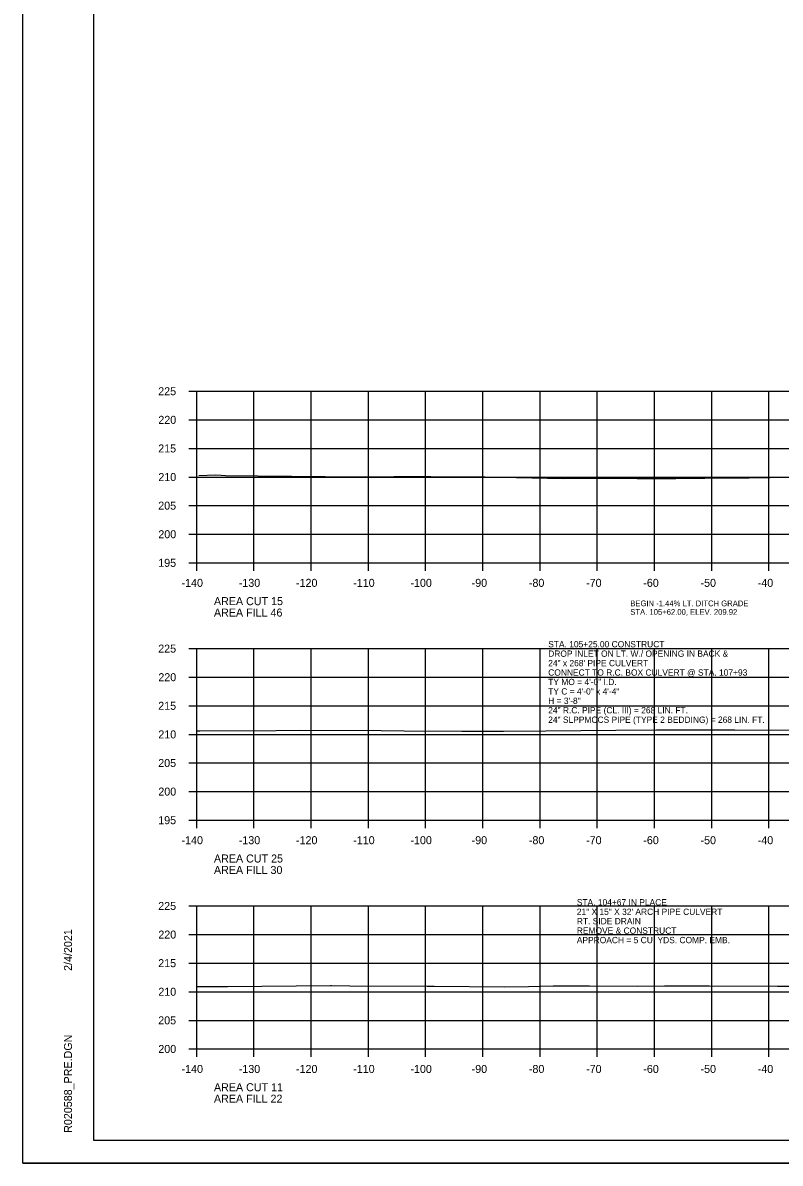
# Model space of a CAD drawing. Extents: x 1368968 to 1369915, y 377395 to 380381.
# Drawn here: x 1368967.7 to 1369100.1, y 378687.7 to 378887.1 of the extents above; entities that cross this region are included whole.
import ezdxf

# ---------------------------------------------------------------- set-up
doc = ezdxf.new("R2010")
doc.units = 0
for name, color, linetype in [('Default', 7, 'Continuous'), ('S_BREAKLINE_ANNOT', 7, 'Continuous'), ('S_BRIDGE', 7, 'Continuous'), ('S_BRIDGE_ANNOT', 7, 'Continuous'), ('S_CONTOUR_MAJOR', 7, 'Continuous'), ('S_CTL_TABLE', 7, 'Continuous'), ('S_DITCHLINE_ANNOT', 7, 'Continuous'), ('S_DROP_INLET', 7, 'Continuous')]:
    doc.layers.add(name, color=color, linetype=linetype)

msp = doc.modelspace()

# ---------------------------------------------------------------- linework, layer by layer
at = {"layer": 'S_BREAKLINE_ANNOT'}
for p, q in [((1368996.73, 378822.7), (1368998.13, 378822.7)), ((1368998.13, 378792.7), (1368998.13, 378822.7)), ((1368996.73, 378817.7), (1368998.13, 378817.7)), ((1368996.73, 378812.7), (1368998.13, 378812.7)), ((1368996.73, 378807.7), (1368998.13, 378807.7)), ((1368996.73, 378802.7), (1368998.13, 378802.7)), ((1368996.73, 378797.7), (1368998.13, 378797.7)), ((1368996.73, 378792.7), (1368998.13, 378792.7)), ((1368998.13, 378792.7), (1369278.13, 378792.7)), ((1368998.13, 378791.3), (1368998.13, 378792.7)), ((1369008.13, 378791.3), (1369008.13, 378792.7)), ((1369018.13, 378791.3), (1369018.13, 378792.7)), ((1369028.13, 378791.3), (1369028.13, 378792.7)), ((1369038.13, 378791.3), (1369038.13, 378792.7)), ((1369048.13, 378791.3), (1369048.13, 378792.7)), ((1369058.13, 378791.3), (1369058.13, 378792.7)), ((1369068.13, 378791.3), (1369068.13, 378792.7)), ((1369078.13, 378791.3), (1369078.13, 378792.7)), ((1369088.13, 378791.3), (1369088.13, 378792.7)), ((1369098.13, 378791.3), (1369098.13, 378792.7)), ((1368996.73, 378777.7), (1368998.13, 378777.7)), ((1368998.13, 378747.7), (1368998.13, 378777.7)), ((1368996.73, 378772.7), (1368998.13, 378772.7)), ((1368996.73, 378767.7), (1368998.13, 378767.7)), ((1368996.73, 378762.7), (1368998.13, 378762.7)), ((1368996.73, 378757.7), (1368998.13, 378757.7)), ((1368996.73, 378752.7), (1368998.13, 378752.7)), ((1368996.73, 378747.7), (1368998.13, 378747.7)), ((1368998.13, 378747.7), (1369278.13, 378747.7)), ((1368998.13, 378746.3), (1368998.13, 378747.7)), ((1369008.13, 378746.3), (1369008.13, 378747.7)), ((1369018.13, 378746.3), (1369018.13, 378747.7)), ((1369028.13, 378746.3), (1369028.13, 378747.7)), ((1369038.13, 378746.3), (1369038.13, 378747.7)), ((1369048.13, 378746.3), (1369048.13, 378747.7)), ((1369058.13, 378746.3), (1369058.13, 378747.7)), ((1369068.13, 378746.3), (1369068.13, 378747.7)), ((1369078.13, 378746.3), (1369078.13, 378747.7)), ((1369088.13, 378746.3), (1369088.13, 378747.7)), ((1369098.13, 378746.3), (1369098.13, 378747.7)), ((1368996.73, 378732.7), (1368998.13, 378732.7)), ((1368998.13, 378707.7), (1368998.13, 378732.7)), ((1368996.73, 378727.7), (1368998.13, 378727.7)), ((1368996.73, 378722.7), (1368998.13, 378722.7)), ((1368996.73, 378717.7), (1368998.13, 378717.7)), ((1368996.73, 378712.7), (1368998.13, 378712.7)), ((1368996.73, 378707.7), (1368998.13, 378707.7)), ((1368998.13, 378707.7), (1369278.13, 378707.7)), ((1368998.13, 378706.3), (1368998.13, 378707.7)), ((1369008.13, 378706.3), (1369008.13, 378707.7)), ((1369018.13, 378706.3), (1369018.13, 378707.7)), ((1369028.13, 378706.3), (1369028.13, 378707.7)), ((1369038.13, 378706.3), (1369038.13, 378707.7)), ((1369048.13, 378706.3), (1369048.13, 378707.7)), ((1369058.13, 378706.3), (1369058.13, 378707.7)), ((1369068.13, 378706.3), (1369068.13, 378707.7)), ((1369078.13, 378706.3), (1369078.13, 378707.7)), ((1369088.13, 378706.3), (1369088.13, 378707.7)), ((1369098.13, 378706.3), (1369098.13, 378707.7))]:
    msp.add_line(p, q, dxfattribs=at)
at = {"layer": 'S_BRIDGE_ANNOT'}
for p, q in [((1368980.13, 378691.7), (1368980.13, 378897.16)), ((1368980.13, 378691.7), (1368980.13, 378691.7)), ((1369296.31, 378691.7), (1368980.13, 378691.7))]:
    msp.add_line(p, q, dxfattribs=at)
at = {"layer": 'S_CTL_TABLE'}
for points in [[(1368998.49, 378807.95), (1369001.46, 378808.06), (1369002.38, 378808.04), (1369003.16, 378807.95), (1369008.8, 378807.9), (1369026.43, 378807.75), (1369028.74, 378807.73), (1369032.56, 378807.78), (1369039.05, 378807.78), (1369048.56, 378807.72), (1369062.14, 378807.47), (1369062.82, 378807.48), (1369075.07, 378807.45), (1369081.09, 378807.46), (1369081.86, 378807.46), (1369092.02, 378807.54), (1369094.58, 378807.57), (1369094.68, 378807.57), (1369102.03, 378807.68)], [(1368998.13, 378763.31), (1368998.68, 378763.31), (1369012.03, 378763.38), (1369016.19, 378763.42), (1369030.35, 378763.38), (1369034.39, 378763.35), (1369044.47, 378763.29), (1369051.73, 378763.24), (1369059.11, 378763.33), (1369071.37, 378763.42), (1369078.46, 378763.49), (1369081.62, 378763.51), (1369092.18, 378763.48), (1369103.18, 378763.42)], [(1368998.13, 378718.62), (1369003, 378718.62), (1369003.48, 378718.62), (1369021.5, 378718.78), (1369021.69, 378718.78), (1369024.86, 378718.76), (1369038.41, 378718.67), (1369039, 378718.67), (1369039.64, 378718.66), (1369051.92, 378718.57), (1369056.1, 378718.63), (1369060.43, 378718.73), (1369066.79, 378718.74), (1369075.19, 378718.7), (1369079.89, 378718.73), (1369087.66, 378718.71), (1369099.64, 378718.66), (1369104.13, 378718.65)]]:
    msp.add_lwpolyline(points, dxfattribs=at)
at = {"layer": 'S_DITCHLINE_ANNOT'}
for p, q in [((1368998.13, 378822.7), (1369278.13, 378822.7)), ((1368998.13, 378792.7), (1368998.13, 378822.7)), ((1369008.13, 378792.7), (1369008.13, 378822.7)), ((1369018.13, 378792.7), (1369018.13, 378822.7)), ((1369028.13, 378792.7), (1369028.13, 378822.7)), ((1369038.13, 378792.7), (1369038.13, 378822.7)), ((1369048.13, 378792.7), (1369048.13, 378822.7)), ((1369058.13, 378792.7), (1369058.13, 378822.7)), ((1369068.13, 378792.7), (1369068.13, 378822.7)), ((1369078.13, 378792.7), (1369078.13, 378822.7)), ((1369088.13, 378792.7), (1369088.13, 378822.7)), ((1369098.13, 378792.7), (1369098.13, 378822.7)), ((1368998.13, 378817.7), (1369278.13, 378817.7)), ((1368998.13, 378812.7), (1369278.13, 378812.7)), ((1368998.13, 378807.7), (1369278.13, 378807.7)), ((1368998.13, 378802.7), (1369278.13, 378802.7)), ((1368998.13, 378797.7), (1369278.13, 378797.7)), ((1368998.13, 378792.7), (1369278.13, 378792.7)), ((1368998.13, 378777.7), (1369278.13, 378777.7)), ((1368998.13, 378747.7), (1368998.13, 378777.7)), ((1369008.13, 378747.7), (1369008.13, 378777.7)), ((1369018.13, 378747.7), (1369018.13, 378777.7)), ((1369028.13, 378747.7), (1369028.13, 378777.7)), ((1369038.13, 378747.7), (1369038.13, 378777.7)), ((1369048.13, 378747.7), (1369048.13, 378777.7)), ((1369058.13, 378747.7), (1369058.13, 378777.7)), ((1369068.13, 378747.7), (1369068.13, 378777.7)), ((1369078.13, 378747.7), (1369078.13, 378777.7)), ((1369088.13, 378747.7), (1369088.13, 378777.7)), ((1369098.13, 378747.7), (1369098.13, 378777.7)), ((1368998.13, 378772.7), (1369278.13, 378772.7)), ((1368998.13, 378767.7), (1369278.13, 378767.7)), ((1368998.13, 378762.7), (1369278.13, 378762.7)), ((1368998.13, 378757.7), (1369278.13, 378757.7)), ((1368998.13, 378752.7), (1369278.13, 378752.7)), ((1368998.13, 378747.7), (1369278.13, 378747.7)), ((1368998.13, 378732.7), (1369278.13, 378732.7)), ((1368998.13, 378707.7), (1368998.13, 378732.7)), ((1369008.13, 378707.7), (1369008.13, 378732.7)), ((1369018.13, 378707.7), (1369018.13, 378732.7)), ((1369028.13, 378707.7), (1369028.13, 378732.7)), ((1369038.13, 378707.7), (1369038.13, 378732.7)), ((1369048.13, 378707.7), (1369048.13, 378732.7)), ((1369058.13, 378707.7), (1369058.13, 378732.7)), ((1369068.13, 378707.7), (1369068.13, 378732.7)), ((1369078.13, 378707.7), (1369078.13, 378732.7)), ((1369088.13, 378707.7), (1369088.13, 378732.7)), ((1369098.13, 378707.7), (1369098.13, 378732.7)), ((1368998.13, 378727.7), (1369278.13, 378727.7)), ((1368998.13, 378722.7), (1369278.13, 378722.7)), ((1368998.13, 378717.7), (1369278.13, 378717.7)), ((1368998.13, 378712.7), (1369278.13, 378712.7)), ((1368998.13, 378707.7), (1369278.13, 378707.7))]:
    msp.add_line(p, q, dxfattribs=at)
at = {"layer": 'S_DROP_INLET'}
msp.add_line((1368967.73, 378687.73), (1369301.07, 378687.73), dxfattribs=at)
for points in [[(1368967.73, 378901.06), (1369301.07, 378901.06), (1369301.07, 378687.72), (1368967.73, 378687.72)], [(1369214.05, 378897.16), (1369214.05, 378887.28), (1369249.79, 378887.28), (1369249.79, 378884.36), (1369272.99, 378884.36), (1369272.99, 378860.03), (1369296.31, 378860.03), (1369296.31, 378691.7), (1368980.13, 378691.7), (1368980.13, 378897.16)]]:
    msp.add_lwpolyline(points, close=True, dxfattribs=at)

# ---------------------------------------------------------------- texts
at = {"layer": 'Default'}
for s, p in [('STA. 105+25.00 CONSTRUCT', (1369059.55, 378777.92)), ('DROP INLET ON LT. W./ OPENING IN BACK &', (1369059.55, 378776.27)), ('24" x 268\' PIPE CULVERT', (1369059.55, 378774.62)), ('CONNECT TO R.C. BOX CULVERT @ STA. 107+93 ', (1369059.55, 378772.97)), ('TY MO = 4\'-0" I.D.', (1369059.55, 378771.32)), ('TY C = 4\'-0" x 4\'-4"', (1369059.55, 378769.67)), ('H = 3\'-8"', (1369059.55, 378768.02)), ('24" R.C. PIPE (CL. III) = 268 LIN. FT.', (1369059.55, 378766.37)), ('24" SLPPMCCS PIPE (TYPE 2 BEDDING) = 268 LIN. FT.', (1369059.55, 378764.72)), ('STA. 104+67 IN PLACE', (1369064.55, 378732.79)), ('21" X 15" X 32\' ARCH PIPE CULVERT', (1369064.55, 378731.14)), ('RT. SIDE DRAIN', (1369064.55, 378729.49)), ('REMOVE & CONSTRUCT ', (1369064.55, 378727.84)), ('APPROACH = 5 CU. YDS. COMP. EMB.', (1369064.55, 378726.19))]:
    msp.add_text(s, height=1.1, dxfattribs=at).set_placement(p)
at = {"layer": 'S_BRIDGE'}
for s, p in [('225', (1368991.39, 378822)), ('220', (1368991.41, 378817)), ('215', (1368991.39, 378812)), ('210', (1368991.41, 378807)), ('205', (1368991.39, 378802)), ('200', (1368991.41, 378797)), ('195', (1368991.39, 378792)), ('-140', (1368995.47, 378788.5)), ('-130', (1369005.47, 378788.5)), ('-120', (1369015.47, 378788.5)), ('-110', (1369025.47, 378788.5)), ('-100', (1369035.47, 378788.5)), ('-90', (1369046.17, 378788.5)), ('-80', (1369056.17, 378788.5)), ('-70', (1369066.17, 378788.5)), ('-60', (1369076.17, 378788.5)), ('-50', (1369086.17, 378788.5)), ('-40', (1369096.17, 378788.5)), ('AREA CUT 15', (1369001.13, 378785.3)), ('AREA FILL 46', (1369001.13, 378783.3)), ('225', (1368991.39, 378777)), ('220', (1368991.41, 378772)), ('215', (1368991.39, 378767)), ('210', (1368991.41, 378762)), ('205', (1368991.39, 378757)), ('200', (1368991.41, 378752)), ('195', (1368991.39, 378747)), ('-140', (1368995.47, 378743.5)), ('-130', (1369005.47, 378743.5)), ('-120', (1369015.47, 378743.5)), ('-110', (1369025.47, 378743.5)), ('-100', (1369035.47, 378743.5)), ('-90', (1369046.17, 378743.5)), ('-80', (1369056.17, 378743.5)), ('-70', (1369066.17, 378743.5)), ('-60', (1369076.17, 378743.5)), ('-50', (1369086.17, 378743.5)), ('-40', (1369096.17, 378743.5)), ('AREA CUT 25', (1369001.13, 378740.3)), ('AREA FILL 30', (1369001.13, 378738.3)), ('225', (1368991.39, 378732)), ('220', (1368991.41, 378727)), ('215', (1368991.39, 378722)), ('210', (1368991.41, 378717)), ('205', (1368991.39, 378712)), ('200', (1368991.41, 378707)), ('-140', (1368995.47, 378703.5)), ('-130', (1369005.47, 378703.5)), ('-120', (1369015.47, 378703.5)), ('-110', (1369025.47, 378703.5)), ('-100', (1369035.47, 378703.5)), ('-90', (1369046.17, 378703.5)), ('-80', (1369056.17, 378703.5)), ('-70', (1369066.17, 378703.5)), ('-60', (1369076.17, 378703.5)), ('-50', (1369086.17, 378703.5)), ('-40', (1369096.17, 378703.5)), ('AREA CUT 11', (1369001.13, 378700.3)), ('AREA FILL 22', (1369001.13, 378698.3))]:
    msp.add_text(s, height=1.4, dxfattribs=at).set_placement(p)
at = {"layer": 'S_BRIDGE_ANNOT'}
for s, p in [('2/4/2021', (1368976.32, 378721.35)), ('R020588_PRE.DGN', (1368976.32, 378693.03))]:
    msp.add_text(s, height=1.4, rotation=90, dxfattribs=at).set_placement(p)
at = {"layer": 'S_CONTOUR_MAJOR'}
for s, p in [('BEGIN -1.44% LT. DITCH GRADE', (1369073.89, 378785.11)), ('BEGIN -1.44% LT. DITCH GRADE', (1369073.89, 378785.11)), ('BEGIN -1.44% LT. DITCH GRADE', (1369073.89, 378785.11)), ('STA. 105+62.00, ELEV. 209.92', (1369073.9, 378783.61)), ('STA. 105+62.00, ELEV. 209.92', (1369073.9, 378783.61)), ('STA. 105+62.00, ELEV. 209.92', (1369073.9, 378783.61))]:
    msp.add_text(s, height=1, dxfattribs=at).set_placement(p)

doc.saveas('drawing.dxf')
